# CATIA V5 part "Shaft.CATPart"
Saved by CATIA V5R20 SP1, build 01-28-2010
Part number: Shaft
Bounding box of the stored display mesh (mm): x -10.997 to 10.997, y 0 to 134, z -10.875 to 10.875
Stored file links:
  D:\v5_r20\psrt_files_downloaded\c14\c14-catia-v5r20-figr-14-26 & 27\Part & Asm\Shaft.CATPart
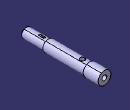
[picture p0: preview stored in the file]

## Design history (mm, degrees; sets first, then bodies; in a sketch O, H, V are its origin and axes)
Body1 (main body)
  Sketch1 on yz-plane, origin (0, 0, 0), H (0, 1, 0), V (0, 0, 1)
    line L1 (0, 0) -> (0, 8)
    line L2 (0, 8) -> (39, 8)
    line L3 (39, 8) -> (39, 9.5)
    line L4 (39, 9.5) -> (109, 9.5)
    line L5 (109, 9.5) -> (109, 11)
    line L6 (109, 11) -> (134, 11)
    line L7 (134, 11) -> (134, 0)
    point P7 (134, 0)
    line L8 (134, 0) -> (0, 0)
    length L1 = 8
    length L8 = 134
    length L7 = 11
    distance L4 L8 = 9.5
    length L6 = 25
    length L4 = 70
    vertical: L1 V, L3 V, L5 V, L7 V
    horizontal: L2 H, L4 H, L6 H, L8 H
    coincidence: P7 H
  Shaft1: profile Sketch1, axis edge of Sketch1, angle 360
  Chamfer1: length 1.5, angle 45, on 1 edge
  Sketch2 on xy-plane, origin (0, 0, 0), H (1, 0, 0), V (0, 1, 0)
    circle A1 centre (0, 97) radius 4.15
    point P1 (0, 97)
    reference projected line E1 (-11, 109) -> (11, 109) from edge of Shaft1
    radius A1 = 4.15
    distance E1 P1 = 12
    coincidence: P1 V
  Pocket1: profile Sketch2, direction (0, 0, -1), length 20, mirrored extent
  Sketch3 on face of Shaft1, origin (0, 134, 0), H (-1, 0, 0), V (0, 0, 1)
    circle A1 centre (0, 0) radius 4.15
    radius A1 = 4.15
  Pocket2: profile Sketch3, direction (0, -1, 0), length 44
  Sketch4 on yz-plane, origin (0, 0, 0), H (0, 1, 0), V (0, 0, 1)
    point P1 (23, 8)
    line L1 (23, 8) -> (33, 8)
    arc A1 centre (28, 12.899) radius 7 from (23, 8) to (33, 8) ccw
    reference projected line E1 (39, -9.5) -> (39, 9.5) from edge of Shaft1
    length L1 = 10
    distance L1 H = 8
    distance P1 E1 = 16
    radius A1 = 7
    horizontal: L1 H
  Pocket3: profile Sketch4, direction (-1, 0, 0), length 1.6, mirrored extent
